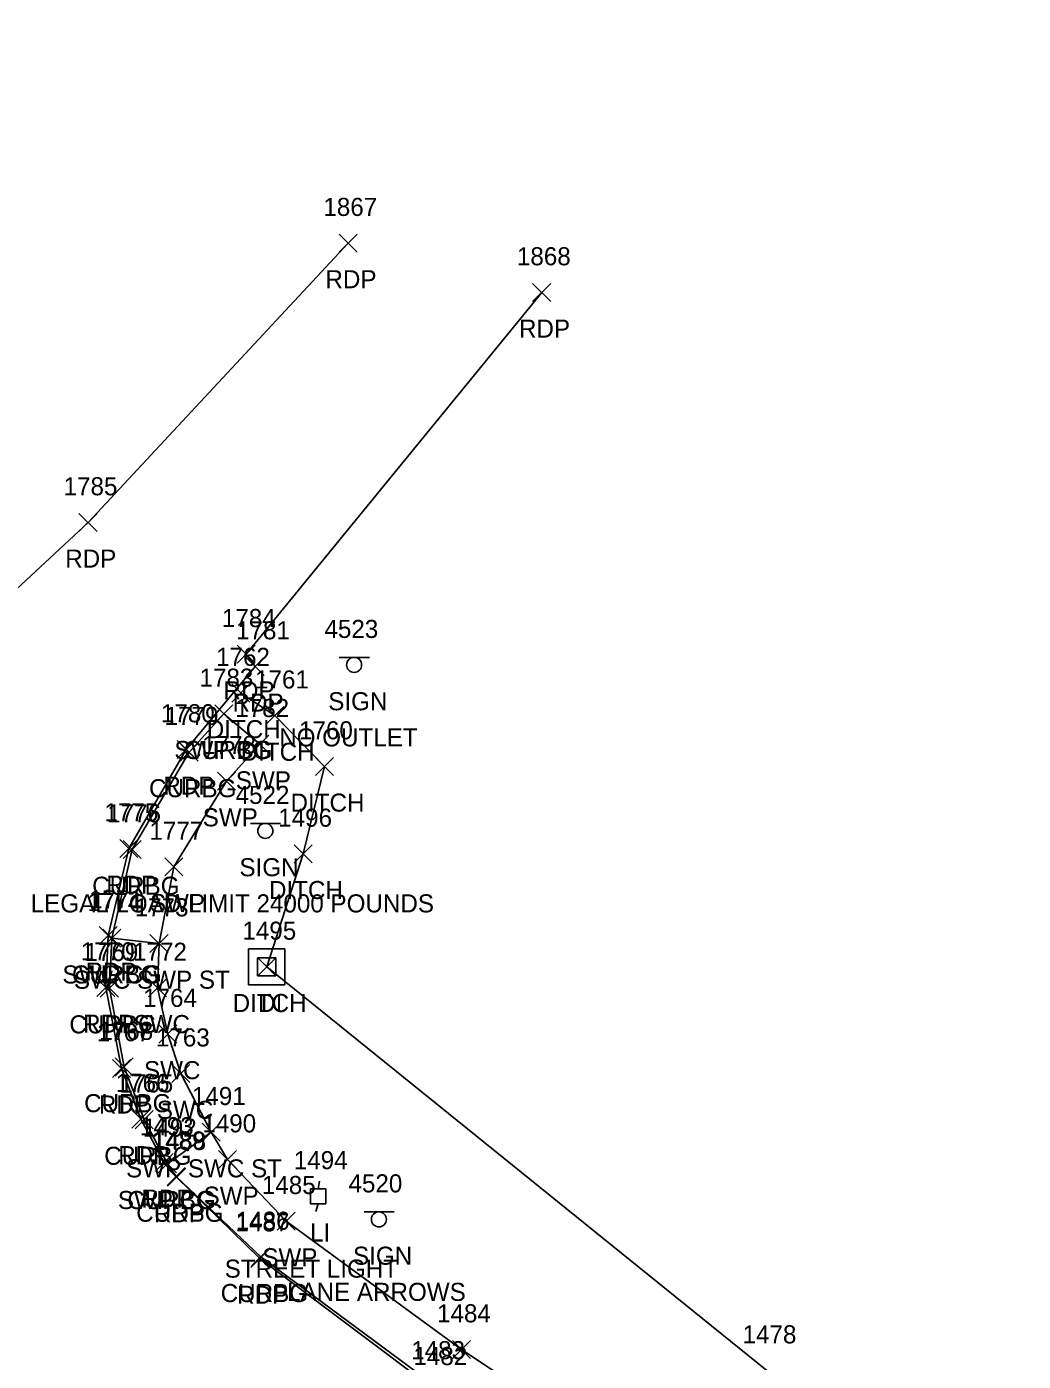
# Model space of a CAD drawing. Extents: x 1690689 to 1696275, y 438760 to 444007.
# Drawn here: x 1691985.8 to 1692096, y 439182.5 to 439330.1 of the extents above; entities that cross this region are included whole.
import ezdxf

# ---------------------------------------------------------------- set-up
doc = ezdxf.new("R2010")
doc.units = 0
for name, color, linetype in [('D_A', 7, 'Continuous'), ('D_I', 7, 'Continuous'), ('D_TIC', 7, 'Continuous'), ('DD', 7, 'Continuous'), ('DS', 7, 'Continuous'), ('P_A', 7, 'Continuous'), ('P_I', 7, 'Continuous'), ('P_TIC', 7, 'Continuous'), ('PET', 7, 'Continuous'), ('R_A', 7, 'Continuous'), ('R_I', 7, 'Continuous'), ('R_TIC', 7, 'Continuous'), ('RC', 7, 'Continuous'), ('RSW', 7, 'Continuous'), ('S_A', 7, 'Continuous'), ('S_C', 7, 'Continuous'), ('S_I', 7, 'Continuous'), ('SSGN', 7, 'Continuous'), ('U_A', 7, 'Continuous'), ('U_C', 7, 'Continuous'), ('U_I', 7, 'Continuous'), ('ULP', 7, 'Continuous')]:
    doc.layers.add(name, color=color, linetype=linetype)

msp = doc.modelspace()

# ---------------------------------------------------------------- linework, layer by layer
at = {"layer": 'D_TIC'}
for points in [[(1692008.52, 439255.4), (1692010.52, 439257.4)], [(1692010.52, 439255.4), (1692008.52, 439257.4)], [(1692012.27, 439252.9), (1692014.27, 439254.9)], [(1692014.27, 439252.9), (1692012.27, 439254.9)], [(1692017.77, 439247.28), (1692019.77, 439249.28)], [(1692019.77, 439247.28), (1692017.77, 439249.28)], [(1692015.4, 439237.61), (1692017.4, 439239.61)], [(1692017.4, 439237.61), (1692015.4, 439239.61)], [(1692011.38, 439225.11), (1692013.38, 439227.11)], [(1692013.38, 439225.11), (1692011.38, 439227.11)]]:
    msp.add_lwpolyline(points, dxfattribs=at)
at = {"layer": 'DD'}
msp.add_lwpolyline([(1692601.69, 439017.79), (1692563.37, 439021.21), (1692508.43, 439031.44), (1692465.47, 439040.14), (1692415.19, 439051.66), (1692376.4, 439060.91), (1692339.07, 439071.12), (1692282.68, 439087.44), (1692232.86, 439105.49), (1692192.88, 439120.62), (1692157.57, 439136.03), (1692114.74, 439157.79), (1692067.68, 439181.46), (1692012.38, 439226.11), (1692016.4, 439238.61), (1692018.77, 439248.28), (1692013.27, 439253.9), (1692009.52, 439256.4)], dxfattribs=at)
at = {"layer": 'DS'}
for p, q in [((1692010.37, 439228.11), (1692014.37, 439228.11)), ((1692010.37, 439224.11), (1692010.37, 439228.11)), ((1692014.37, 439228.11), (1692014.37, 439224.11)), ((1692011.37, 439225.11), (1692011.37, 439227.11)), ((1692011.37, 439227.11), (1692013.37, 439227.11)), ((1692012.38, 439226.11), (1692012.38, 439226.11)), ((1692012.38, 439226.11), (1692012.38, 439226.11)), ((1692013.37, 439227.11), (1692013.37, 439225.11)), ((1692013.37, 439225.11), (1692011.37, 439225.11)), ((1692014.37, 439224.11), (1692010.37, 439224.11))]:
    msp.add_line(p, q, dxfattribs=at)
at = {"layer": 'P_TIC'}
for points in [[(1692020.38, 439305.17), (1692022.38, 439307.17)], [(1692022.38, 439305.17), (1692020.38, 439307.17)], [(1692041.78, 439299.71), (1692043.78, 439301.71)], [(1692043.78, 439299.71), (1692041.78, 439301.71)], [(1691991.62, 439274.27), (1691993.62, 439276.27)], [(1691993.62, 439274.27), (1691991.62, 439276.27)], [(1691991.62, 439274.27), (1691993.62, 439276.27)], [(1691993.62, 439274.27), (1691991.62, 439276.27)], [(1692009.11, 439259.69), (1692011.11, 439261.69)], [(1692011.11, 439259.69), (1692009.11, 439261.69)], [(1692009.11, 439259.69), (1692011.11, 439261.69)], [(1692011.11, 439259.69), (1692009.11, 439261.69)], [(1692010.11, 439258.34), (1692012.11, 439260.34)], [(1692012.11, 439258.34), (1692010.11, 439260.34)], [(1692002.46, 439249.16), (1692004.46, 439251.16)], [(1692004.46, 439249.16), (1692002.46, 439251.16)], [(1691996.14, 439238.21), (1691998.14, 439240.21)], [(1691998.14, 439238.21), (1691996.14, 439240.21)], [(1691993.86, 439228.58), (1691995.86, 439230.58)], [(1691995.86, 439228.58), (1691993.86, 439230.58)], [(1691993.6, 439222.82), (1691995.6, 439224.82)], [(1691995.6, 439222.82), (1691993.6, 439224.82)], [(1691995.33, 439213.88), (1691997.33, 439215.88)], [(1691997.33, 439213.88), (1691995.33, 439215.88)], [(1691997.47, 439208.28), (1691999.47, 439210.28)], [(1691999.47, 439208.28), (1691997.47, 439210.28)], [(1692000.04, 439203.48), (1692002.04, 439205.48)], [(1692002.04, 439203.48), (1692000.04, 439205.48)], [(1692001.42, 439201.85), (1692003.42, 439203.85)], [(1692003.42, 439201.85), (1692001.42, 439203.85)], [(1692010.62, 439192.84), (1692012.62, 439194.84)], [(1692012.62, 439192.84), (1692010.62, 439194.84)]]:
    msp.add_lwpolyline(points, dxfattribs=at)
at = {"layer": 'PET'}
for points in [[(1691992.62, 439275.27), (1691979.94, 439263.46), (1691976.88, 439259.74), (1691970.97, 439254.36), (1691965.57, 439251.25), (1691960.33, 439249.79), (1691957.17, 439249.18), (1691949.06, 439249.61), (1691944.52, 439250.6), (1691940.06, 439252), (1691934.23, 439255.84), (1691921.54, 439266.1), (1691889.35, 439293.07), (1691851.08, 439328.77), (1691838.86, 439341.34)], [(1691992.62, 439275.27), (1692021.38, 439306.17)], [(1692010.11, 439260.69), (1692042.78, 439300.71)], [(1692506.42, 439007.58), (1692409.86, 439027.99), (1692378.72, 439035.13), (1692333.82, 439046.83), (1692278.1, 439062.9), (1692234.78, 439077.7), (1692205.8, 439088.84), (1692153.42, 439111.21), (1692107.02, 439133.53), (1692055.61, 439162.86), (1692031.29, 439179.06), (1692011.62, 439193.84), (1692002.42, 439202.85), (1692001.04, 439204.48), (1691998.47, 439209.28), (1691996.33, 439214.88), (1691994.6, 439223.82), (1691994.86, 439229.58), (1691997.14, 439239.21), (1692003.46, 439250.16), (1692011.11, 439259.34), (1692010.11, 439260.69)]]:
    msp.add_lwpolyline(points, dxfattribs=at)
at = {"layer": 'R_TIC'}
for points in [[(1692006.64, 439253.1), (1692008.64, 439255.1)], [(1692008.64, 439253.1), (1692006.64, 439255.1)], [(1692006.64, 439253.1), (1692008.64, 439255.1)], [(1692008.64, 439253.1), (1692006.64, 439255.1)], [(1692002.79, 439248.87), (1692004.79, 439250.87)], [(1692004.79, 439248.87), (1692002.79, 439250.87)], [(1692010.6, 439249.74), (1692012.6, 439251.74)], [(1692012.6, 439249.74), (1692010.6, 439251.74)], [(1692006.93, 439245.65), (1692008.93, 439247.65)], [(1692008.93, 439245.65), (1692006.93, 439247.65)], [(1691996.49, 439238.08), (1691998.49, 439240.08)], [(1691998.49, 439238.08), (1691996.49, 439240.08)], [(1692001.1, 439236.16), (1692003.1, 439238.16)], [(1692003.1, 439236.16), (1692001.1, 439238.16)], [(1691994.26, 439228.27), (1691996.26, 439230.27)], [(1691996.26, 439228.27), (1691994.26, 439230.27)], [(1691994.26, 439228.27), (1691996.26, 439230.27)], [(1691996.26, 439228.27), (1691994.26, 439230.27)], [(1691999.47, 439227.69), (1692001.47, 439229.69)], [(1692001.47, 439227.69), (1691999.47, 439229.69)], [(1691999.47, 439227.69), (1692001.47, 439229.69)], [(1692001.47, 439227.69), (1691999.47, 439229.69)], [(1691993.98, 439222.75), (1691995.98, 439224.75)], [(1691995.98, 439222.75), (1691993.98, 439224.75)], [(1691999.29, 439222.78), (1692001.29, 439224.78)], [(1692001.29, 439222.78), (1691999.29, 439224.78)], [(1692000.45, 439217.68), (1692002.45, 439219.68)], [(1692002.45, 439217.68), (1692000.45, 439219.68)], [(1691995.61, 439214.03), (1691997.61, 439216.03)], [(1691997.61, 439214.03), (1691995.61, 439216.03)], [(1692001.87, 439213.3), (1692003.87, 439215.3)], [(1692003.87, 439213.3), (1692001.87, 439215.3)], [(1691997.83, 439208.21), (1691999.83, 439210.21)], [(1691999.83, 439208.21), (1691997.83, 439210.21)], [(1692005.24, 439206.82), (1692007.24, 439208.82)], [(1692007.24, 439206.82), (1692005.24, 439208.82)], [(1692005.24, 439206.82), (1692007.24, 439208.82)], [(1692007.24, 439206.82), (1692005.24, 439208.82)], [(1692000.39, 439203.32), (1692002.39, 439205.32)], [(1692002.39, 439203.32), (1692000.39, 439205.32)], [(1692000.39, 439203.32), (1692002.39, 439205.32)], [(1692002.39, 439203.32), (1692000.39, 439205.32)], [(1692007.04, 439203.8), (1692009.04, 439205.8)], [(1692009.04, 439203.8), (1692007.04, 439205.8)], [(1692001.37, 439201.91), (1692003.37, 439203.91)], [(1692003.37, 439201.91), (1692001.37, 439203.91)], [(1692013.53, 439196.98), (1692015.53, 439198.98)], [(1692015.53, 439196.98), (1692013.53, 439198.98)], [(1692010.71, 439193.03), (1692012.71, 439195.03)], [(1692012.71, 439193.03), (1692010.71, 439195.03)], [(1692032.9, 439182.79), (1692034.9, 439184.79)], [(1692034.9, 439182.79), (1692032.9, 439184.79)]]:
    msp.add_lwpolyline(points, dxfattribs=at)
at = {"layer": 'RC'}
msp.add_lwpolyline([(1692458.66, 439018.07), (1692409.83, 439028.32), (1692378.84, 439035.52), (1692333.85, 439047.39), (1692278.2, 439063.36), (1692234.93, 439078.32), (1692206.05, 439089.01), (1692153.68, 439111.65), (1692107.21, 439133.95), (1692055.41, 439163.27), (1692031.04, 439179.71), (1692011.71, 439194.03), (1692002.37, 439202.91), (1692001.39, 439204.32), (1691998.83, 439209.21), (1691996.61, 439215.03), (1691994.98, 439223.75), (1691995.26, 439229.27), (1691997.49, 439239.08), (1692003.79, 439249.87), (1692007.64, 439254.1)], dxfattribs=at)
at = {"layer": 'RSW'}
for points in [[(1692000.47, 439228.69), (1692002.1, 439237.16), (1692007.93, 439246.65), (1692011.6, 439250.74), (1692007.64, 439254.1)], [(1692006.24, 439207.82), (1692002.87, 439214.3), (1692001.45, 439218.68), (1692000.29, 439223.78), (1692000.47, 439228.69), (1691995.26, 439229.27)], [(1692665.59, 438979.47), (1692633.47, 438986.11), (1692606.01, 438992.31), (1692555.68, 439002.49), (1692507.66, 439012.62), (1692459.75, 439022.83), (1692410.78, 439033.39), (1692380.42, 439040.26), (1692334.91, 439052.16), (1692279.52, 439068.27), (1692236.35, 439083.17), (1692207.73, 439093.85), (1692155.83, 439116.19), (1692109.79, 439138.3), (1692057.98, 439167.75), (1692033.9, 439183.79), (1692014.53, 439197.98), (1692008.04, 439204.8), (1692006.24, 439207.82), (1692001.39, 439204.32)]]:
    msp.add_lwpolyline(points, dxfattribs=at)
at = {"layer": 'SSGN'}
for p, q in [((1692020.39, 439260.34), (1692023.73, 439260.34)), ((1692022.04, 439259.51), (1692022.04, 439259.51)), ((1692010.57, 439241.98), (1692013.91, 439241.98)), ((1692012.22, 439241.15), (1692012.22, 439241.15)), ((1692023.14, 439199.01), (1692026.47, 439199.01)), ((1692024.78, 439198.18), (1692024.78, 439198.18))]:
    msp.add_line(p, q, dxfattribs=at)
for centre in [(1692022.04, 439259.51), (1692012.22, 439241.15), (1692024.78, 439198.18)]:
    msp.add_circle(centre, 0.833, dxfattribs=at)
at = {"layer": 'ULP'}
for p, q in [((1692018.23, 439202.4), (1692018.07, 439201.56)), ((1692017.23, 439199.9), (1692017.23, 439201.56)), ((1692017.23, 439201.56), (1692018.9, 439201.56)), ((1692018.07, 439200.73), (1692018.07, 439200.73)), ((1692018.9, 439201.56), (1692018.9, 439199.9)), ((1692018.9, 439199.9), (1692017.23, 439199.9)), ((1692017.82, 439199.06), (1692018.07, 439199.9))]:
    msp.add_line(p, q, dxfattribs=at)

# ---------------------------------------------------------------- texts
at = {"layer": 'D_A'}
for s, p in [('DITCH', (1692005.75, 439251.4)), ('DITCH', (1692009.5, 439248.9)), ('DITCH', (1692015.01, 439243.28)), ('DITCH', (1692012.63, 439233.61)), ('DITCH', (1692008.61, 439221.11)), ('DI', (1692011.43, 439221.11))]:
    msp.add_text(s, height=2, dxfattribs=at).set_placement(p)
at = {"layer": 'D_I'}
for s, p in [('1762', (1692006.78, 439259.4)), ('1761', (1692011.09, 439256.9)), ('1760', (1692015.95, 439251.28)), ('1496', (1692013.65, 439241.61)), ('1495', (1692009.69, 439229.11)), ('1495', (1692009.69, 439229.11)), ('1478', (1692064.99, 439184.46))]:
    msp.add_text(s, height=2, dxfattribs=at).set_placement(p)
at = {"layer": 'P_A'}
for p in [(1692018.87, 439301.17), (1692040.27, 439295.71), (1691990.1, 439270.27), (1691990.1, 439270.27), (1692007.6, 439255.69), (1692007.6, 439255.69), (1692008.6, 439254.34), (1692000.95, 439245.16), (1691994.63, 439234.21), (1691992.35, 439224.58), (1691992.08, 439218.82), (1691993.82, 439209.88), (1691995.96, 439204.28), (1691998.53, 439199.48), (1691999.91, 439197.85), (1692009.11, 439188.84)]:
    msp.add_text('RDP', height=2, dxfattribs=at).set_placement(p)
at = {"layer": 'P_I'}
for s, p in [('1867', (1692018.64, 439309.17)), ('1868', (1692040.04, 439303.71)), ('1785', (1691989.92, 439278.27)), ('1785', (1691989.92, 439278.27)), ('1784', (1692007.42, 439263.69)), ('1784', (1692007.42, 439263.69)), ('1781', (1692008.99, 439262.34)), ('1780', (1692000.68, 439253.16)), ('1775', (1691994.44, 439242.21)), ('1771', (1691992.73, 439232.58)), ('1770', (1691991.82, 439226.82)), ('1767', (1691993.59, 439217.88)), ('1766', (1691995.68, 439212.28)), ('1493', (1691998.35, 439207.48)), ('1488', (1691999.73, 439205.85)), ('1487', (1692008.93, 439196.84)), ('1482', (1692028.6, 439182.06))]:
    msp.add_text(s, height=2, dxfattribs=at).set_placement(p)
at = {"layer": 'R_A'}
for s, p in [('SWP CG', (1692002.17, 439249.1)), ('CURBG', (1692003.22, 439249.1)), ('CURBG', (1691999.37, 439244.87)), ('SWP', (1692008.96, 439245.74)), ('SWP', (1692005.3, 439241.65)), ('CURBG', (1691993.08, 439234.08)), ('SWP', (1691999.46, 439232.16)), ('SWC CG', (1691989.79, 439224.27)), ('CURBG', (1691990.84, 439224.27)), ('SWC SWP ST', (1691991.06, 439223.69)), ('SWC SWP ST', (1691991.06, 439223.69)), ('CURBG', (1691990.56, 439218.75)), ('SWC', (1691997.65, 439218.78)), ('SWC', (1691998.81, 439213.68)), ('CURBG', (1691992.19, 439210.03)), ('SWC', (1692000.23, 439209.3)), ('CURBG', (1691994.41, 439204.21)), ('SWP SWC ST', (1691996.83, 439202.82)), ('SWP SWC ST', (1691996.83, 439202.82)), ('SWP CG', (1691995.92, 439199.32)), ('CURBG', (1691996.97, 439199.32)), ('SWP', (1692005.4, 439199.8)), ('CURBG', (1691997.95, 439197.91)), ('SWP', (1692011.89, 439192.98)), ('CURBG', (1692007.29, 439189.03))]:
    msp.add_text(s, height=2, dxfattribs=at).set_placement(p)
at = {"layer": 'R_I'}
for s, p in [('1783', (1692004.95, 439257.1)), ('1783', (1692004.95, 439257.1)), ('1782', (1692008.9, 439253.74)), ('1779', (1692001.09, 439252.87)), ('1778', (1692005.24, 439249.65)), ('1776', (1691994.74, 439242.08)), ('1777', (1691999.41, 439240.16)), ('1774', (1691992.56, 439232.27)), ('1774', (1691992.56, 439232.27)), ('1773', (1691997.78, 439231.69)), ('1773', (1691997.78, 439231.69)), ('1769', (1691992.23, 439226.75)), ('1772', (1691997.6, 439226.78)), ('1764', (1691998.71, 439221.68)), ('1768', (1691993.87, 439218.03)), ('1763', (1692000.13, 439217.3)), ('1765', (1691996.09, 439212.21)), ('1491', (1692004.11, 439210.82)), ('1491', (1692004.11, 439210.82)), ('1490', (1692005.26, 439207.8)), ('1492', (1691998.69, 439207.32)), ('1492', (1691998.69, 439207.32)), ('1489', (1691999.67, 439205.91)), ('1485', (1692011.84, 439200.98)), ('1486', (1692008.96, 439197.03)), ('1484', (1692031.21, 439186.79)), ('1483', (1692028.35, 439182.71))]:
    msp.add_text(s, height=2, dxfattribs=at).set_placement(p)
at = {"layer": 'S_A'}
for p in [(1692019.18, 439254.49), (1692009.36, 439236.13), (1692021.92, 439193.16)]:
    msp.add_text('SIGN', height=2, dxfattribs=at).set_placement(p)
at = {"layer": 'S_C'}
for s, p in [('NO OUTLET', (1692013.76, 439250.49)), ('LEGAL LOAD LIMIT 24000 POUNDS', (1691986.28, 439232.13)), ('LANE ARROWS', (1692014.62, 439189.16))]:
    msp.add_text(s, height=2, dxfattribs=at).set_placement(p)
at = {"layer": 'S_I'}
for s, p in [('4523', (1692018.76, 439262.49)), ('4522', (1692008.94, 439244.13)), ('4520', (1692021.42, 439201.16))]:
    msp.add_text(s, height=2, dxfattribs=at).set_placement(p)
at = {"layer": 'U_A'}
msp.add_text('LI', height=2, dxfattribs=at).set_placement((1692017.17, 439195.73))
at = {"layer": 'U_C'}
msp.add_text('STREET LIGHT', height=2, dxfattribs=at).set_placement((1692007.73, 439191.73))
at = {"layer": 'U_I'}
msp.add_text('1494', height=2, dxfattribs=at).set_placement((1692015.37, 439203.73))

doc.saveas('drawing.dxf')
